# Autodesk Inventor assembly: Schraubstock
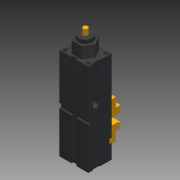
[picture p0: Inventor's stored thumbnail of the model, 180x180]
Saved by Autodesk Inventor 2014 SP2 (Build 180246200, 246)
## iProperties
Created: 2015-06
Part Number: Schraubstock
Document SubType Name: Assembly
Designer: e_krauts
Mass: 4334.15 g
Surface Area: 5057.15 cm^2
Volume: 4334.15 cm^3
Density: 1 g/cm^3
Sending System: SolidWorks 2011
Last Author: e_boekem
Author: e_krauts
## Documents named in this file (5)
- C:\Users\e_krauts\AppData\Local\SolidCAM Temporary Files\PRISMA_AUFSPANNUNG-3\Schraubstock.iam
- C:\Users\e_krauts\AppData\Local\SolidCAM Temporary Files\PRISMA_AUFSPANNUNG-3\Backe20x40.ipt
- C:\Users\e_krauts\AppData\Local\SolidCAM Temporary Files\PRISMA_AUFSPANNUNG-3\Unterteil.ipt
- C:\Users\e_krauts\AppData\Local\SolidCAM Temporary Files\PRISMA_AUFSPANNUNG-3\Backe 40 x 20 ohne.ipt
- C:\Users\e_krauts\AppData\Local\SolidCAM Temporary Files\PRISMA_AUFSPANNUNG-3\Spindel.ipt
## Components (4 placed, 4 different names)
1. Backe20x40:1 — Passend:2, Fluchtend:1
2. Unterteil:1 — Passend:1, Passend:2, Passend:4, Passend:5, Fluchtend:1
3. Backe 40 x 20 ohne:1 — Passend:3, Passend:4
4. Spindel:2 — Passend:1, Passend:3, Passend:5
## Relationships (6: Mate 5, Flush 1)
- Passend:1 [Mate]: Unterteil:1 ↔ Spindel:2
- Passend:2 [Mate]: Backe20x40:1 ↔ Unterteil:1
- Passend:3 [Mate]: Backe 40 x 20 ohne:1 ↔ Spindel:2
- Passend:4 [Mate]: Unterteil:1 ↔ Backe 40 x 20 ohne:1
- Passend:5 [Mate]: Unterteil:1 ↔ Spindel:2
- Fluchtend:1 [Flush]: Backe20x40:1 ↔ Unterteil:1
